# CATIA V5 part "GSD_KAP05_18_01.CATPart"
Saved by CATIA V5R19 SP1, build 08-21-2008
Part number: GSD_PROJECT_01
Definition: Beispielmodell für die Funktion Projektion / Projection
Description: CATIA V5 Flächenmodellierung  Copyright (c) 2009 Maik Hertha IT Consultants
Bounding box of the stored display mesh (mm): x -85.524 to 85.379, y -80.431 to 120, z -13.314 to 106.792
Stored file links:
  C:\Users\Maik\CAD Daten\modelle\gsd_buch_uebung\GSD_KAP05_18_01.CATPart
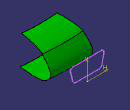
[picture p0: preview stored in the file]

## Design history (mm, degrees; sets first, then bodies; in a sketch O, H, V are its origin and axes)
AxisSystem1 "Absolute Axis System": origin (0, 0, 0), X (1, 0, 0), Y (0, 1, 0), Z (0, 0, 1)
Set1 "Project Support"
  Set2 "Sketches.1"
    Sketch1 on face of AxisSystem1, origin (0, 0, 0), H (0, 1, 0), V (0, 0, 1)
      construction line L1 (71.6536, 26.9434) -> (53.0305, -19.0034)
      construction line L2 (53.0305, -19.0034) -> (-63.9738, -19.0034)
      construction line L3 (71.6536, 26.9434) -> (43.8508, 96.3904)
      construction line L4 (43.8508, 96.3904) -> (-63.0791, 96.3904)
      construction line L5 (-70.7603, 106.7922) -> (-16.9173, 106.7922)
      construction line L6 (24.4664, 86.8546) -> (2.869, 108.5885)
      point P10 (-10.5947, 99.9)
      coniccurve C1
      construction line L7 (24.4664, 86.8546) -> (56.7085, 54.4086)
      construction line L8 (50.7518, 13.2158) -> (86.758, 47.4895)
      point P15 (55.4022, 50.3861)
      coniccurve C2
      point P16 (41.3943, 4.3085)
      construction line L9 (41.3943, 4.3085) -> (17.4972, -18.4387)
      construction line L10 (-76.841, -13.3144) -> (-37.4365, -13.3144)
      coniccurve C3
      line L11 (41.3943, 4.3085) -> (50.7518, 13.2158)
      point P20 (41.3943, 4.3085)
      horizontal: L2 H, L4 H, L5 H, L10 H
      parallelism: L11 L8, L9 L8
      coincidence: P16 P20
      tangency: C1 C2
    Sketch2 on face of AxisSystem1, origin (0, 0, 0), H (1, 0, 0), V (0, 1, 0)
      construction line L1 (-120, 0) -> (-69.4764, 10.579)
      construction line L2 (120, 0) -> (70, 10)
      point P5 (0, 10)
      coniccurve C1
  Set3 "Helpers.1"
    Plane1: type Offset, Offset 80, RefPlane face of AxisSystem1
    Plane2: type Offset, Offset 80, RefPlane face of AxisSystem1, reversed
    Intersect1: ToIntersect1 Plane1, ToIntersect2 Sketch2
    Intersect2: ToIntersect1 Plane2, ToIntersect2 Sketch2
  Plane3 "Relimiter.1": type Normal, Curve Sketch2, RefPoint Intersect1
  Plane4 "Relimiter.2": type Normal, Curve Sketch2, RefPoint Intersect2
  Sweep1: type Unspec, Guide Sketch2, Profile Sketch1, RelimElem1 Plane3, RelimElem2 Plane4
Set4 "Projected"
  Sketch3 on Plane5, origin (0, 120, 0), H (-1, 0, 0), V (0, 0, 1)
    line L1 (-57.651, 80) -> (57.651, 80)
    line L2 (67.4325, 67.9209) -> (59.7721, 31.8813)
    line L3 (-67.4325, 67.9209) -> (-59.7721, 31.8813)
    line L4 (-45.0998, 20) -> (45.0998, 20)
    construction line L5 (0, 115.8375) -> (0, -33.918)
    point P1 (0, 115.8375)
    arc A1 centre (57.651, 70) radius 10 from (57.651, 80) to (67.4325, 67.9209) cw
    arc A2 centre (-57.651, 70) radius 10 from (-57.651, 80) to (-67.4325, 67.9209) ccw
    arc A3 centre (-45.0998, 35) radius 15 from (-45.0998, 20) to (-59.7721, 31.8813) cw
    arc A4 centre (45.0998, 35) radius 15 from (45.0998, 20) to (59.7721, 31.8813) ccw
    axis line L6 (-68.6384, 0) -> (72.6064, 0)
    point P15 (-68.6384, 0)
    construction line L7 (48.9149, -19.1974) -> (70, 80)
    point P17 (48.9149, -19.1974)
    construction line L8 (-48.6403, -20.4896) -> (-70, 80)
    point P18 (-48.6403, -20.4896)
    construction line L9 (-70, 80) -> (70, 80)
    point P19 (-70, 80)
    point P20 (70, 80)
    curve C1
    angle L5 L3 = 12 {= Sketch3.angle(L5 L2)}
    angle L5 L2 = 12
    radius A1 = 10
    radius A2 = 10 {= Sketch3.radius(A1)}
    radius A3 = 15 {= Sketch3.radius(A4)}
    radius A4 = 15
    distance L6 L4 = 20
    distance L4 L1 = 60
    distance L5 P19 = 70 {= Sketch3.distance(P20 L5)}
    distance P20 L5 = 70
    horizontal: L1 H, L4 H, L6 H
    coincidence: P1 V, P15 H, P17 L2, P18 L3, L8 L3, L2 L7, L9 L1
    vertical: L5 V
    tangency: A1 L1, A1 L2, A2 L1, A2 L3, A3 L4, A3 L3, A4 L4, A4 L2, L7 A1, L8 A2, L9 A1
  Plane5: type Offset, Offset 120, RefPlane face of AxisSystem1
Body1 (main body)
